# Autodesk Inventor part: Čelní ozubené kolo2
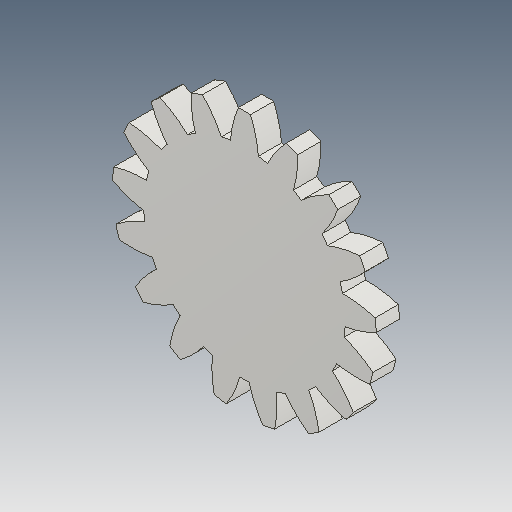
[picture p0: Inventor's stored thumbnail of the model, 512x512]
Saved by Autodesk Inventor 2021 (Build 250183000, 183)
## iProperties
CustomPartVersion: 1
Created: 2024-11
Part Number: Čelní ozubené kolo2
Material: Steel
Document SubType Name: Modeling
Designer: tatulinek
Categories: <?xml version="1.0" encoding="UTF-16"?> <MemberInstance><Categories><FamilyTemplate><FamilyTemplateParameter ValueType="xs:double" Id="1" ObjectReferenceKey="da
Density: 1 g/cm^3
Appearance: Steel
Author: tatulinek
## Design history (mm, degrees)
sketch "Sketch1"
  geometry: C1 r 114 at (0, 0)
  constraints: 1 centre point
  dimensions: "d0" = 228 diameter of C1 (= da_da)
extrude "Extrusion1" new body sketch "Sketch1" distance "d1" = 20 (= da_b); taper "d2" = 0 deg
workplane "Work Plane2"
sketch "Sketch2"
  geometry: C1 r 114 at (0, 0) reference; C2 r 102 at (0, 0)
  constraints: 1 centre point, 1 coincident
  dimensions: "d3" = 204 diameter of C2 (= da_d)
feature "Roztečný průměr" sketch "Sketch2" dims "d4" = 10, "d5" = 0
workplane "Work Plane8"
workplane "Work Plane9"
feature "Čelní ozubené kolo" dims "d5" = 0, "da_b" = 20, "da_d" = 204, "da_aw" = 174, "da_da" = 228, "da_df" = 174, "da_dw" = 204, angle "da_beta" = 0 deg, "da_lefttooth" = 0, "da_righttooth" = 0
body "Solid1"
body "Srf1"
other parameters: "d16" = 174 (= da_aw), "d17" = 0, "d34" = 1.848 (computed from da_z), "d39" = 0, "d41" = 0, "d43" = 174 (= da_aw), "d46" = 174 (= da_aw), "d47" = 0, "d48" = 0
